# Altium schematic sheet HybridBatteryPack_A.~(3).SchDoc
size A4
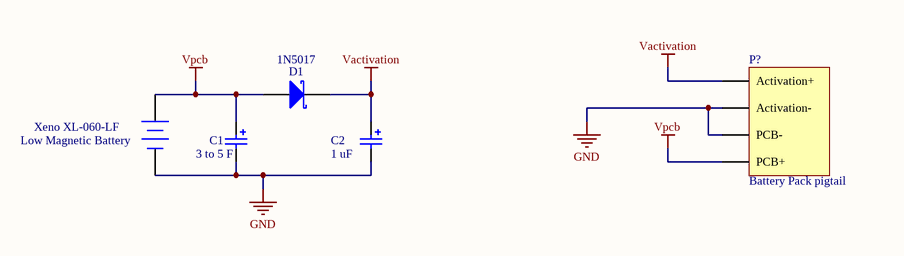
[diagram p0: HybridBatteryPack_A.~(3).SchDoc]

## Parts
C1  value 3 to 5 F  [POLAR0.8]  (hidden comment: Cap Pol2)
C2  value 1 uF  [POLAR0.8]  (hidden comment: Cap Pol2)
D1  1N5017  [DO-204AL]
P?  Battery Pack pigtail  [HDR1X4]
Xeno_XL-060-LF  Low Magnetic Battery  [BAT-2]

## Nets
GND: C1.2 C2.2 P?.2(Activation-) P?.3(PCB-) Xeno_XL-060-LF.2(-)
Vactivation: C2.1 D1.2(K) P?.1(Activation+)
Vpcb: C1.1 D1.1(A) P?.4(PCB+) Xeno_XL-060-LF.1(+)

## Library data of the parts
C1 C2 = Cap Pol2: Polarized Capacitor (Axial)
D1 = Diode 11DQ03: Schottky Rectifier
P? = Battery Pack pigtail: Header, 4-Pin
Xeno_XL-060-LF = Battery: Multicell Battery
